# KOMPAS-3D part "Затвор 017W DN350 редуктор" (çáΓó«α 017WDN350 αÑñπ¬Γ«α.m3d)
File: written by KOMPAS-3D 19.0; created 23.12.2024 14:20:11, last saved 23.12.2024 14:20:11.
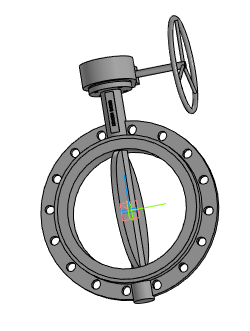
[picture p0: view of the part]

Document properties: Автор: Евгений; Полное имя файла: ..\Затвор 017WDN350 редуктор.a3d

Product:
- Part/product: Затвор 017W DN350 редуктор
    Масса: 71.8471

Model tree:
1. Операция без истории:1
